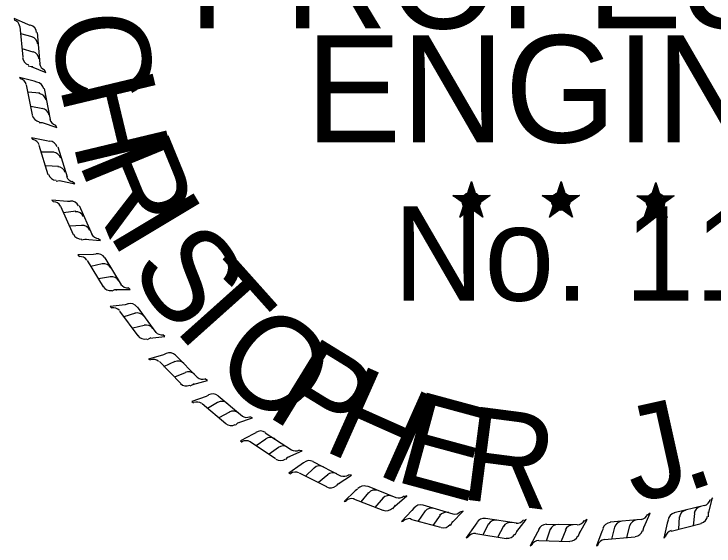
# Model space of a CAD drawing. Extents: x -1771525.8 to -1771491.7, y -422628.7 to -422606.9.
# Drawn here: x -1771501.136 to -1771499.911, y -422627.329 to -422626.398 of the extents above; entities that cross this region are included whole.
import ezdxf

# ---------------------------------------------------------------- set-up
doc = ezdxf.new("R2010")
doc.units = 0
doc.layers.add('Border 2660-Hwy18 - Stamp-ChrisC', color=7, linetype='Continuous')

msp = doc.modelspace()

# ---------------------------------------------------------------- linework, layer by layer
at = {"layer": 'Border 2660-Hwy18 - Stamp-ChrisC'}
for p, q in [((-1771501.112, -422626.4165), (-1771501.136, -422626.406)), ((-1771501.136, -422626.406), (-1771501.1352, -422626.4097)), ((-1771501.1202, -422626.4742), (-1771501.1255, -422626.4202)), ((-1771501.1075, -422626.4187), (-1771501.112, -422626.4165)), ((-1771501.1045, -422626.4382), (-1771501.124, -422626.433)), ((-1771501.0955, -422626.4307), (-1771501.091, -422626.4855)), ((-1771501.1022, -422626.4652), (-1771501.1217, -422626.4592)), ((-1771501.1112, -422626.4892), (-1771501.106, -422626.49)), ((-1771501.106, -422626.49), (-1771501.0805, -422626.5005)), ((-1771501.106, -422626.49), (-1771501.103, -422626.49)), ((-1771501.0805, -422626.5005), (-1771501.0827, -422626.4967)), ((-1771501.1007, -422626.5162), (-1771501.1262, -422626.5095)), ((-1771501.1262, -422626.5095), (-1771501.1247, -422626.5117)), ((-1771501.0962, -422626.5177), (-1771501.1007, -422626.5162)), ((-1771501.1037, -422626.5747), (-1771501.1142, -422626.5222)), ((-1771501.0835, -422626.529), (-1771501.073, -422626.583)), ((-1771501.091, -422626.5372), (-1771501.112, -422626.535)), ((-1771501.0857, -422626.5642), (-1771501.1067, -422626.5605)), ((-1771501.0917, -422626.5882), (-1771501.0865, -422626.5882)), ((-1771501.0865, -422626.5882), (-1771501.061, -422626.5972)), ((-1771501.0865, -422626.5882), (-1771501.0842, -422626.589)), ((-1771501.061, -422626.5972), (-1771501.0632, -422626.5927)), ((-1771501.079, -422626.6205), (-1771501.1052, -422626.6152)), ((-1771501.1052, -422626.6152), (-1771501.103, -422626.6182)), ((-1771501.076, -422626.6797), (-1771501.0917, -422626.6287)), ((-1771501.0737, -422626.6212), (-1771501.079, -422626.6205)), ((-1771501.0595, -422626.631), (-1771501.043, -422626.6835)), ((-1771501.0662, -422626.64), (-1771501.088, -422626.64)), ((-1771501.058, -422626.6655), (-1771501.0805, -422626.664)), ((-1771501.0625, -422626.691), (-1771501.0565, -422626.6895)), ((-1771501.0565, -422626.6895), (-1771501.0295, -422626.6955)), ((-1771501.0565, -422626.6895), (-1771501.0542, -422626.6902)), ((-1771501.0295, -422626.6955), (-1771501.034, -422626.6917)), ((-1771500.3357, -422626.6917), (-1771500.341, -422626.715)), ((-1771500.3357, -422626.6917), (-1771500.3395, -422626.7157)), ((-1771500.3357, -422626.6917), (-1771500.3372, -422626.7157)), ((-1771500.3357, -422626.7262), (-1771500.3357, -422626.6917)), ((-1771500.3357, -422626.6917), (-1771500.329, -422626.7157)), ((-1771500.3357, -422626.6917), (-1771500.3305, -422626.7157)), ((-1771500.3357, -422626.6917), (-1771500.3335, -422626.715)), ((-1771500.179, -422626.6917), (-1771500.1842, -422626.715)), ((-1771500.179, -422626.6917), (-1771500.1827, -422626.7157)), ((-1771500.179, -422626.6917), (-1771500.1805, -422626.7157)), ((-1771500.179, -422626.7262), (-1771500.179, -422626.6917)), ((-1771500.179, -422626.6917), (-1771500.173, -422626.7157)), ((-1771500.179, -422626.6917), (-1771500.1745, -422626.7157)), ((-1771500.179, -422626.6917), (-1771500.1767, -422626.715)), ((-1771500.0132, -422626.6932), (-1771500.0185, -422626.7157)), ((-1771500.0132, -422626.6932), (-1771500.017, -422626.7165)), ((-1771500.0132, -422626.6932), (-1771500.0147, -422626.7165)), ((-1771500.0132, -422626.727), (-1771500.0132, -422626.6932)), ((-1771500.0132, -422626.6932), (-1771500.0072, -422626.7165)), ((-1771500.0132, -422626.6932), (-1771500.0087, -422626.7165)), ((-1771500.0132, -422626.6932), (-1771500.011, -422626.7165)), ((-1771500.368, -422626.7157), (-1771500.3357, -422626.7262)), ((-1771500.368, -422626.7157), (-1771500.344, -422626.718)), ((-1771500.368, -422626.7157), (-1771500.344, -422626.7202)), ((-1771500.368, -422626.7157), (-1771500.3455, -422626.7217)), ((-1771500.368, -422626.7157), (-1771500.3455, -422626.7247)), ((-1771500.368, -422626.7157), (-1771500.3462, -422626.727)), ((-1771500.368, -422626.7157), (-1771500.3462, -422626.7292)), ((-1771500.3027, -422626.7157), (-1771500.3357, -422626.7262)), ((-1771500.3027, -422626.7157), (-1771500.332, -422626.718)), ((-1771500.3027, -422626.7157), (-1771500.3297, -422626.7202)), ((-1771500.3027, -422626.7157), (-1771500.3297, -422626.7225)), ((-1771500.3027, -422626.7157), (-1771500.3237, -422626.724)), ((-1771500.3027, -422626.7157), (-1771500.3222, -422626.7255)), ((-1771500.3027, -422626.7157), (-1771500.3207, -422626.7262)), ((-1771500.212, -422626.7157), (-1771500.179, -422626.7262)), ((-1771500.212, -422626.7157), (-1771500.188, -422626.718)), ((-1771500.212, -422626.7157), (-1771500.188, -422626.7202)), ((-1771500.212, -422626.7157), (-1771500.1887, -422626.7217)), ((-1771500.212, -422626.7157), (-1771500.1895, -422626.7247)), ((-1771500.212, -422626.7157), (-1771500.1895, -422626.727)), ((-1771500.212, -422626.7157), (-1771500.1895, -422626.7292)), ((-1771500.1467, -422626.7157), (-1771500.179, -422626.7262)), ((-1771500.1467, -422626.7157), (-1771500.1752, -422626.718)), ((-1771500.1467, -422626.7157), (-1771500.173, -422626.7202)), ((-1771500.1467, -422626.7157), (-1771500.173, -422626.7225)), ((-1771500.1467, -422626.7157), (-1771500.167, -422626.724)), ((-1771500.1467, -422626.7157), (-1771500.1655, -422626.7255)), ((-1771500.1467, -422626.7157), (-1771500.164, -422626.7262)), ((-1771500.0462, -422626.7165), (-1771500.0132, -422626.727)), ((-1771500.0462, -422626.7165), (-1771500.0222, -422626.7195)), ((-1771500.0462, -422626.7165), (-1771500.0222, -422626.721)), ((-1771500.0462, -422626.7165), (-1771500.023, -422626.7225)), ((-1771500.0462, -422626.7165), (-1771500.023, -422626.7262)), ((-1771500.0462, -422626.7165), (-1771500.0237, -422626.7285)), ((-1771500.0462, -422626.7165), (-1771500.0237, -422626.73)), ((-1771499.981, -422626.7165), (-1771500.0132, -422626.727)), ((-1771499.981, -422626.7165), (-1771500.0095, -422626.7187)), ((-1771499.981, -422626.7165), (-1771500.0072, -422626.7217)), ((-1771499.981, -422626.7165), (-1771500.0072, -422626.7232)), ((-1771499.981, -422626.7165), (-1771500.002, -422626.7255)), ((-1771499.981, -422626.7165), (-1771499.9997, -422626.7262)), ((-1771499.981, -422626.7165), (-1771499.9982, -422626.7277)), ((-1771501.0422, -422626.7262), (-1771501.07, -422626.724)), ((-1771501.07, -422626.724), (-1771501.067, -422626.727)), ((-1771501.0377, -422626.7262), (-1771501.0422, -422626.7262)), ((-1771500.356, -422626.754), (-1771500.3357, -422626.7262)), ((-1771500.356, -422626.754), (-1771500.3455, -422626.7277)), ((-1771500.3155, -422626.754), (-1771500.3357, -422626.7262)), ((-1771500.3155, -422626.754), (-1771500.3282, -422626.727)), ((-1771500.3155, -422626.754), (-1771500.326, -422626.7262)), ((-1771500.1992, -422626.754), (-1771500.179, -422626.7262)), ((-1771500.1992, -422626.754), (-1771500.1887, -422626.7277)), ((-1771500.1587, -422626.754), (-1771500.179, -422626.7262)), ((-1771500.1587, -422626.754), (-1771500.1715, -422626.727)), ((-1771500.1587, -422626.754), (-1771500.17, -422626.7262)), ((-1771500.0335, -422626.7547), (-1771500.0132, -422626.727)), ((-1771499.993, -422626.7547), (-1771500.0132, -422626.727)), ((-1771499.993, -422626.7547), (-1771500.0065, -422626.7277)), ((-1771499.993, -422626.7547), (-1771500.0042, -422626.7277)), ((-1771501.0317, -422626.7847), (-1771501.0542, -422626.7352)), ((-1771501.022, -422626.7337), (-1771500.9995, -422626.7847)), ((-1771500.356, -422626.754), (-1771500.344, -422626.7307)), ((-1771500.356, -422626.754), (-1771500.3425, -422626.7322)), ((-1771500.356, -422626.754), (-1771500.3357, -422626.7337)), ((-1771500.356, -422626.754), (-1771500.3395, -422626.7345)), ((-1771500.356, -422626.754), (-1771500.335, -422626.736)), ((-1771500.3155, -422626.754), (-1771500.3357, -422626.7337)), ((-1771500.3155, -422626.754), (-1771500.3357, -422626.7367)), ((-1771500.3155, -422626.754), (-1771500.332, -422626.7345)), ((-1771500.3155, -422626.754), (-1771500.329, -422626.7307)), ((-1771500.1992, -422626.754), (-1771500.1872, -422626.7307)), ((-1771500.1992, -422626.754), (-1771500.1857, -422626.7322)), ((-1771500.1992, -422626.754), (-1771500.179, -422626.7337)), ((-1771500.1992, -422626.754), (-1771500.1827, -422626.7345)), ((-1771500.1992, -422626.754), (-1771500.1782, -422626.736)), ((-1771500.1587, -422626.754), (-1771500.179, -422626.7337)), ((-1771500.1587, -422626.754), (-1771500.179, -422626.7367)), ((-1771500.1587, -422626.754), (-1771500.176, -422626.7345)), ((-1771500.1587, -422626.754), (-1771500.173, -422626.7307)), ((-1771500.0335, -422626.7547), (-1771500.023, -422626.7292)), ((-1771500.0335, -422626.7547), (-1771500.0215, -422626.7322)), ((-1771500.0335, -422626.7547), (-1771500.02, -422626.733)), ((-1771500.0335, -422626.7547), (-1771500.017, -422626.7352)), ((-1771500.0335, -422626.7547), (-1771500.014, -422626.7352)), ((-1771500.0335, -422626.7547), (-1771500.0125, -422626.7375)), ((-1771499.993, -422626.7547), (-1771500.014, -422626.7352)), ((-1771499.993, -422626.7547), (-1771500.014, -422626.7375)), ((-1771499.993, -422626.7547), (-1771500.0095, -422626.7352)), ((-1771499.993, -422626.7547), (-1771500.0065, -422626.7322)), ((-1771501.028, -422626.7435), (-1771501.0497, -422626.7465)), ((-1771501.0167, -422626.7682), (-1771501.0392, -422626.7697)), ((-1771501.0182, -422626.7937), (-1771501.0122, -422626.7922)), ((-1771501.0122, -422626.7922), (-1771500.9845, -422626.7945)), ((-1771501.0122, -422626.7922), (-1771501.0092, -422626.7922)), ((-1771500.9845, -422626.7945), (-1771500.989, -422626.7915)), ((-1771500.9972, -422626.8192), (-1771501.0242, -422626.82)), ((-1771501.0242, -422626.82), (-1771501.0212, -422626.823)), ((-1771500.9927, -422626.8185), (-1771500.9972, -422626.8192)), ((-1771500.977, -422626.8252), (-1771500.9485, -422626.8725)), ((-1771500.9792, -422626.8755), (-1771501.0077, -422626.8297)), ((-1771500.9815, -422626.8357), (-1771501.0017, -422626.8402)), ((-1771500.9672, -422626.8582), (-1771500.9882, -422626.862)), ((-1771500.9642, -422626.883), (-1771500.9597, -422626.8807)), ((-1771500.9597, -422626.8807), (-1771500.9327, -422626.8807)), ((-1771500.9597, -422626.8807), (-1771500.9567, -422626.8815)), ((-1771500.9327, -422626.8807), (-1771500.9365, -422626.877)), ((-1771500.9417, -422626.907), (-1771500.968, -422626.91)), ((-1771500.968, -422626.91), (-1771500.965, -422626.913)), ((-1771500.9365, -422626.9055), (-1771500.9417, -422626.907)), ((-1771500.9207, -422626.9107), (-1771500.8877, -422626.9557)), ((-1771500.9185, -422626.9617), (-1771500.9507, -422626.9182)), ((-1771500.9237, -422626.922), (-1771500.944, -422626.928)), ((-1771500.908, -422626.9437), (-1771500.9282, -422626.9482)), ((-1771500.872, -422626.9625), (-1771500.8757, -422626.9595)), ((-1771500.9027, -422626.9677), (-1771500.8982, -422626.9655)), ((-1771500.8982, -422626.9655), (-1771500.872, -422626.9625)), ((-1771500.8982, -422626.9655), (-1771500.896, -422626.9647)), ((-1771500.8742, -422626.9947), (-1771500.9005, -422627.0022)), ((-1771500.8697, -422626.9925), (-1771500.8742, -422626.9947)), ((-1771500.8532, -422626.9955), (-1771500.8142, -422627.0352)), ((-1771500.9005, -422627.0022), (-1771500.8975, -422627.0037)), ((-1771500.8442, -422627.045), (-1771500.8817, -422627.0067)), ((-1771500.8547, -422627.0067), (-1771500.8742, -422627.0157)), ((-1771500.8367, -422627.0262), (-1771500.8555, -422627.0337)), ((-1771500.8277, -422627.0487), (-1771500.8232, -422627.0465)), ((-1771500.8232, -422627.0465), (-1771500.7977, -422627.0397)), ((-1771500.8232, -422627.0465), (-1771500.821, -422627.045)), ((-1771500.7977, -422627.0397), (-1771500.8022, -422627.0367)), ((-1771500.8, -422627.0675), (-1771500.8247, -422627.0765)), ((-1771500.7955, -422627.0652), (-1771500.8, -422627.0675)), ((-1771500.779, -422627.0667), (-1771500.7362, -422627.102)), ((-1771500.8247, -422627.0765), (-1771500.8217, -422627.0787)), ((-1771500.7655, -422627.1155), (-1771500.8067, -422627.0802)), ((-1771500.7797, -422627.078), (-1771500.7977, -422627.0885)), ((-1771500.7587, -422627.0952), (-1771500.7775, -422627.105)), ((-1771500.7445, -422627.114), (-1771500.719, -422627.105)), ((-1771500.719, -422627.105), (-1771500.7235, -422627.1035)), ((-1771500.7482, -422627.1177), (-1771500.7445, -422627.114)), ((-1771500.7445, -422627.114), (-1771500.7422, -422627.1132)), ((-1771500.713, -422627.1312), (-1771500.7175, -422627.1335)), ((-1771500.6965, -422627.1312), (-1771500.6507, -422627.1612)), ((-1771500.7175, -422627.1335), (-1771500.74, -422627.1455)), ((-1771500.6957, -422627.1425), (-1771500.7122, -422627.1537)), ((-1771500.74, -422627.1455), (-1771500.737, -422627.1477)), ((-1771500.6785, -422627.177), (-1771500.7227, -422627.147)), ((-1771500.6732, -422627.1567), (-1771500.6897, -422627.1687)), ((-1771500.6567, -422627.174), (-1771500.632, -422627.1627)), ((-1771500.632, -422627.1627), (-1771500.6365, -422627.162)), ((-1771500.6605, -422627.1777), (-1771500.6567, -422627.174)), ((-1771500.6567, -422627.174), (-1771500.6545, -422627.1732)), ((-1771500.6132, -422627.1815), (-1771500.5637, -422627.207)), ((-1771500.6335, -422627.1867), (-1771500.6552, -422627.2017)), ((-1771500.6297, -422627.1837), (-1771500.6335, -422627.1867)), ((-1771500.611, -422627.1927), (-1771500.626, -422627.207)), ((-1771500.6552, -422627.2017), (-1771500.6515, -422627.2032)), ((-1771500.5885, -422627.2257), (-1771500.6365, -422627.2017)), ((-1771500.587, -422627.2047), (-1771500.6035, -422627.2182)), ((-1771500.569, -422627.2205), (-1771500.5457, -422627.2055)), ((-1771500.5457, -422627.2055), (-1771500.551, -422627.2047)), ((-1771500.572, -422627.2242), (-1771500.569, -422627.2205)), ((-1771500.569, -422627.2205), (-1771500.566, -422627.219)), ((-1771500.5352, -422627.2295), (-1771500.539, -422627.2325)), ((-1771500.518, -422627.2242), (-1771500.4677, -422627.2445)), ((-1771500.539, -422627.2325), (-1771500.5585, -422627.2512)), ((-1771500.5157, -422627.2355), (-1771500.5292, -422627.252)), ((-1771500.47, -422627.2595), (-1771500.449, -422627.2415)), ((-1771500.449, -422627.2415), (-1771500.4542, -422627.243)), ((-1771500.5585, -422627.2512), (-1771500.5547, -422627.2505)), ((-1771500.4902, -422627.267), (-1771500.5412, -422627.2475)), ((-1771500.4902, -422627.2452), (-1771500.5045, -422627.2617)), ((-1771499.921, -422627.2722), (-1771499.9142, -422627.2452)), ((-1771499.9142, -422627.2452), (-1771499.9172, -422627.2497)), ((-1771500.473, -422627.264), (-1771500.47, -422627.2595)), ((-1771500.47, -422627.2595), (-1771500.4685, -422627.258)), ((-1771500.44, -422627.267), (-1771500.458, -422627.2865)), ((-1771500.4362, -422627.2632), (-1771500.44, -422627.267)), ((-1771500.4167, -422627.2677), (-1771500.4295, -422627.2865)), ((-1771500.4205, -422627.2572), (-1771500.368, -422627.273)), ((-1771499.981, -422627.2707), (-1771499.9277, -422627.258)), ((-1771500.3905, -422627.2752), (-1771500.4032, -422627.2932)), ((-1771500.3695, -422627.288), (-1771500.35, -422627.2685)), ((-1771500.35, -422627.2685), (-1771500.3552, -422627.27)), ((-1771500.0342, -422627.297), (-1771500.023, -422627.2715)), ((-1771500.023, -422627.2715), (-1771500.0275, -422627.2752)), ((-1771499.972, -422627.2782), (-1771499.9735, -422627.3)), ((-1771499.9457, -422627.2722), (-1771499.948, -422627.294)), ((-1771499.921, -422627.2722), (-1771499.921, -422627.2692)), ((-1771499.921, -422627.2782), (-1771499.921, -422627.2722)), ((-1771500.458, -422627.2865), (-1771500.455, -422627.2857)), ((-1771500.389, -422627.297), (-1771500.4415, -422627.2827)), ((-1771500.3725, -422627.2932), (-1771500.3695, -422627.288)), ((-1771500.3695, -422627.288), (-1771500.368, -422627.2865)), ((-1771500.326, -422627.2887), (-1771500.329, -422627.2925)), ((-1771500.3057, -422627.2902), (-1771500.3155, -422627.3097)), ((-1771500.311, -422627.2805), (-1771500.257, -422627.2887)), ((-1771500.2562, -422627.3037), (-1771500.2397, -422627.2827)), ((-1771500.2397, -422627.2827), (-1771500.2442, -422627.285)), ((-1771500.2052, -422627.291), (-1771500.1505, -422627.2917)), ((-1771500.1467, -422627.3067), (-1771500.1332, -422627.2827)), ((-1771500.1332, -422627.2827), (-1771500.1377, -422627.2857)), ((-1771500.0927, -422627.2872), (-1771500.0387, -422627.282)), ((-1771499.993, -422627.2895), (-1771499.999, -422627.3157)), ((-1771499.9915, -422627.2842), (-1771499.993, -422627.2895)), ((-1771499.9337, -422627.2902), (-1771499.9862, -422627.3037)), ((-1771500.329, -422627.2925), (-1771500.3447, -422627.315)), ((-1771500.2795, -422627.2947), (-1771500.29, -422627.3142)), ((-1771500.2592, -422627.3097), (-1771500.2562, -422627.3037)), ((-1771500.2562, -422627.3037), (-1771500.2555, -422627.3022)), ((-1771500.218, -422627.3007), (-1771500.2202, -422627.3052)), ((-1771500.1977, -422627.3), (-1771500.2052, -422627.321)), ((-1771500.1707, -422627.3007), (-1771500.179, -422627.321)), ((-1771500.1467, -422627.3067), (-1771500.146, -422627.3045)), ((-1771500.1077, -422627.3037), (-1771500.1167, -422627.3292)), ((-1771500.1055, -422627.2992), (-1771500.1077, -422627.3037)), ((-1771500.0852, -422627.2962), (-1771500.0905, -422627.3172)), ((-1771500.059, -422627.2932), (-1771500.0642, -422627.315)), ((-1771500.0357, -422627.303), (-1771500.0342, -422627.297)), ((-1771500.0342, -422627.297), (-1771500.0335, -422627.2947)), ((-1771500.3447, -422627.315), (-1771500.3417, -422627.3135)), ((-1771500.275, -422627.3165), (-1771500.3282, -422627.3082)), ((-1771500.2202, -422627.3052), (-1771500.233, -422627.3292)), ((-1771500.149, -422627.3127), (-1771500.1467, -422627.3067)), ((-1771500.0492, -422627.3135), (-1771500.1032, -422627.3187)), ((-1771499.999, -422627.3157), (-1771499.996, -422627.3127)), ((-1771500.233, -422627.3292), (-1771500.23, -422627.3277)), ((-1771500.164, -422627.3217), (-1771500.218, -422627.3202)), ((-1771500.1167, -422627.3292), (-1771500.1137, -422627.327))]:
    msp.add_line(p, q, dxfattribs=at)
for points in [[(-1771500.3357, -422626.6917), (-1771500.3155, -422626.754), (-1771500.368, -422626.7157), (-1771500.3027, -422626.7157), (-1771500.356, -422626.754), (-1771500.3357, -422626.6917)], [(-1771500.179, -422626.6917), (-1771500.1587, -422626.754), (-1771500.212, -422626.7157), (-1771500.1467, -422626.7157), (-1771500.1992, -422626.754), (-1771500.179, -422626.6917)], [(-1771500.0132, -422626.6932), (-1771499.993, -422626.7547), (-1771500.0462, -422626.7165), (-1771499.981, -422626.7165), (-1771500.0335, -422626.7547), (-1771500.0132, -422626.6932)]]:
    msp.add_lwpolyline(points, dxfattribs=at)
for centre, radius in [((-1771500.3358, -422626.7259), 0.0161), ((-1771500.3358, -422626.7259), 0.0146), ((-1771500.3358, -422626.7259), 0.0136), ((-1771500.3358, -422626.7259), 0.0124), ((-1771500.3358, -422626.7259), 0.0109), ((-1771500.3358, -422626.7259), 0.0101), ((-1771500.3358, -422626.7259), 0.00929), ((-1771500.1793, -422626.7259), 0.0161), ((-1771500.1793, -422626.7259), 0.0146), ((-1771500.1793, -422626.7259), 0.0136), ((-1771500.1793, -422626.7259), 0.0124), ((-1771500.1793, -422626.7259), 0.0109), ((-1771500.1793, -422626.7259), 0.0101), ((-1771500.1793, -422626.7259), 0.00929), ((-1771500.0136, -422626.727), 0.0161), ((-1771500.0136, -422626.727), 0.0146), ((-1771500.0136, -422626.727), 0.0136), ((-1771500.0136, -422626.727), 0.0124), ((-1771500.0136, -422626.727), 0.0109), ((-1771500.3358, -422626.7259), 0.008), ((-1771500.3358, -422626.7259), 0.00701), ((-1771500.3358, -422626.7259), 0.00583), ((-1771500.3358, -422626.7259), 0.00464), ((-1771500.3358, -422626.7259), 0.00346), ((-1771500.3358, -422626.7259), 0.00278), ((-1771500.3358, -422626.7259), 0.00135), ((-1771500.1793, -422626.7259), 0.008), ((-1771500.1793, -422626.7259), 0.00701), ((-1771500.1793, -422626.7259), 0.00583), ((-1771500.1793, -422626.7259), 0.00464), ((-1771500.1793, -422626.7259), 0.00346), ((-1771500.1793, -422626.7259), 0.00278), ((-1771500.1793, -422626.7259), 0.00135), ((-1771500.0136, -422626.727), 0.0101), ((-1771500.0136, -422626.727), 0.00929), ((-1771500.0136, -422626.727), 0.008), ((-1771500.0136, -422626.727), 0.00701), ((-1771500.0136, -422626.727), 0.00583), ((-1771500.0136, -422626.727), 0.00464), ((-1771500.0136, -422626.727), 0.00346), ((-1771500.0136, -422626.727), 0.00278), ((-1771500.0136, -422626.727), 0.00135)]:
    msp.add_circle(centre, radius, dxfattribs=at)
for centre, start, end in [((-1771501.1405, -422626.4227), 9.4933, 68.2812), ((-1771501.1111, -422626.4321), 5.2325, 73.6065), ((-1771501.1091, -422626.4525), 5.2325, 73.6065), ((-1771501.1068, -422626.4789), 5.2325, 73.6065), ((-1771501.1065, -422626.4731), 185.2325, 253.6065), ((-1771501.077, -422626.4825), 189.4933, 248.2812), ((-1771501.1288, -422626.526), 15.7912, 74.579), ((-1771501.0985, -422626.5321), 11.5304, 79.9044), ((-1771501.0944, -422626.5522), 11.5304, 79.9044), ((-1771501.0892, -422626.5781), 11.5304, 79.9044), ((-1771501.0895, -422626.5723), 191.5304, 259.9044), ((-1771501.0592, -422626.5784), 195.7912, 254.579), ((-1771501.1055, -422626.6328), 22.0938, 80.8817), ((-1771501.0747, -422626.6355), 17.8331, 86.207), ((-1771501.0684, -422626.6551), 17.8331, 86.207), ((-1771501.0604, -422626.6803), 17.8331, 86.207), ((-1771501.0613, -422626.6746), 197.8331, 266.207), ((-1771501.0305, -422626.6773), 202.0938, 260.8817), ((-1771501.0674, -422626.7416), 29.1451, 87.9329), ((-1771501.0365, -422626.7405), 24.8843, 93.2583), ((-1771501.0279, -422626.7591), 24.8843, 93.2583), ((-1771501.0168, -422626.7831), 24.8843, 93.2583), ((-1771501.0184, -422626.7776), 204.8843, 273.2583), ((-1771500.9876, -422626.7765), 209.1451, 267.9329), ((-1771501.0204, -422626.8376), 36.0034, 94.7913), ((-1771500.9899, -422626.8328), 31.7427, 100.1166), ((-1771500.979, -422626.8502), 31.7427, 100.1166), ((-1771500.9652, -422626.8728), 31.7427, 100.1166), ((-1771500.9675, -422626.8674), 211.7427, 280.1166), ((-1771500.9369, -422626.8627), 216.0034, 274.7913), ((-1771500.9628, -422626.9271), 40.9505, 99.7383), ((-1771500.9328, -422626.9197), 36.6897, 105.0637), ((-1771500.9205, -422626.9362), 36.6897, 105.0637), ((-1771500.9047, -422626.9574), 36.6897, 105.0637), ((-1771500.9075, -422626.9523), 216.6897, 285.0637), ((-1771500.8775, -422626.9449), 220.9505, 279.7383), ((-1771500.8641, -422627.0059), 44.9655, 113.3394), ((-1771500.8927, -422627.0175), 49.2262, 108.0141), ((-1771500.8495, -422627.0203), 44.9655, 113.3394), ((-1771500.8309, -422627.0391), 44.9655, 113.3394), ((-1771500.8057, -422627.0228), 229.2262, 288.0141), ((-1771500.8344, -422627.0345), 224.9655, 293.3394), ((-1771500.7885, -422627.0778), 50.1902, 118.5642), ((-1771500.816, -422627.092), 54.451, 113.2388), ((-1771500.7727, -422627.0909), 50.1902, 118.5642), ((-1771500.7525, -422627.1079), 50.1902, 118.5642), ((-1771500.7289, -422627.0894), 234.451, 293.2388), ((-1771500.7563, -422627.1036), 230.1902, 298.5642), ((-1771500.7044, -422627.1428), 56.1736, 124.5476), ((-1771500.7303, -422627.1598), 60.4344, 119.2222), ((-1771500.6873, -422627.1542), 56.1736, 124.5476), ((-1771500.6654, -422627.169), 56.1736, 124.5476), ((-1771500.6439, -422627.1481), 240.4344, 299.2222), ((-1771500.6697, -422627.1651), 236.1736, 304.5476), ((-1771500.6196, -422627.1946), 63.0708, 131.4448), ((-1771500.6012, -422627.2039), 63.0708, 131.4448), ((-1771500.6432, -422627.2146), 67.3316, 126.1194), ((-1771500.5777, -422627.2159), 63.0708, 131.4448), ((-1771500.5588, -422627.1926), 247.3316, 306.1194), ((-1771500.5824, -422627.2126), 243.0708, 311.4448), ((-1771500.5238, -422627.2388), 69.0955, 137.4695), ((-1771500.5046, -422627.2461), 69.0955, 137.4695), ((-1771500.48, -422627.2556), 69.0955, 137.4695), ((-1771500.4636, -422627.2304), 253.3563, 312.1441), ((-1771500.5452, -422627.2611), 73.3563, 132.1441), ((-1771499.9323, -422627.2445), 288.1674, 346.9552), ((-1771500.485, -422627.2528), 249.0955, 317.4695), ((-1771500.4247, -422627.272), 73.9909, 142.3649), ((-1771500.405, -422627.2776), 73.9909, 142.3649), ((-1771499.957, -422627.2807), 103.9066, 172.2806), ((-1771499.9313, -422627.2744), 103.9066, 172.2806), ((-1771500.3796, -422627.285), 73.9909, 142.3649), ((-1771500.3654, -422627.2586), 258.2517, 317.0395), ((-1771500.0413, -422627.2684), 279.9249, 338.7128), ((-1771499.977, -422627.2857), 103.9066, 172.2806), ((-1771499.9371, -422627.275), 283.9066, 352.2806), ((-1771500.4441, -422627.2961), 78.2517, 137.0395), ((-1771500.3848, -422627.2826), 253.9909, 322.3649), ((-1771500.3135, -422627.2956), 81.4231, 149.797), ((-1771500.2932, -422627.2986), 81.4231, 149.797), ((-1771500.267, -422627.3026), 81.4231, 149.797), ((-1771500.2564, -422627.2746), 265.6839, 324.4717), ((-1771500.2048, -422627.3061), 89.1628, 157.5368), ((-1771500.1843, -422627.3063), 89.1628, 157.5368), ((-1771500.1578, -422627.3068), 89.1628, 157.5368), ((-1771500.1511, -422627.2776), 273.4236, 332.2115), ((-1771500.0914, -422627.3028), 95.6641, 164.0381), ((-1771500.071, -422627.3007), 95.6641, 164.0381), ((-1771500.0447, -422627.2982), 95.6641, 164.0381), ((-1771500.0505, -422627.2979), 275.6641, 344.0381), ((-1771499.9818, -422627.3162), 108.1674, 166.9552), ((-1771500.3296, -422627.322), 85.6839, 144.4717), ((-1771500.2726, -422627.3009), 261.4231, 329.797), ((-1771500.1635, -422627.3059), 269.1628, 337.5368), ((-1771500.2172, -422627.3344), 93.4236, 152.2115), ((-1771500.1006, -422627.3323), 99.9249, 158.7128)]:
    msp.add_arc(centre, 0.0148, start, end, dxfattribs=at)

# ---------------------------------------------------------------- texts
for s, height, p in [('PROFESSIONAL', 0.187497, (-1771500.8305, -422626.4237)), ('ENGINEER', 0.1875, (-1771500.6257, -422626.6232)), ('No. 11328', 0.165, (-1771500.4726, -422626.8999))]:
    msp.add_text(s, height=height, dxfattribs=at).set_placement(p)
for s, rotation, p in [('C', 275.4459, (-1771501.069, -422626.4003)), ('H', 283.4739, (-1771501.0572, -422626.5237)), ('R', 292.3405, (-1771501.0243, -422626.6566)), ('I', 300.9555, (-1771500.9731, -422626.7794)), ('S', 305.713, (-1771500.9371, -422626.8435)), ('T', 311.8122, (-1771500.8833, -422626.921)), ('O', 320.3433, (-1771500.795, -422627.0188)), ('P', 328.4551, (-1771500.6985, -422627.0987)), ('H', 335.98, (-1771500.5997, -422627.1599)), ('E', 344.8465, (-1771500.4742, -422627.2147)), ('J', 12.5364, (-1771500.0521, -422627.254)), ('R', 352.6229, (-1771500.3583, -422627.2464)), ('.', 18.5518, (-1771499.961, -422627.2354))]:
    msp.add_text(s, height=0.1642, rotation=rotation, dxfattribs=at).set_placement(p)

doc.saveas('drawing.dxf')
